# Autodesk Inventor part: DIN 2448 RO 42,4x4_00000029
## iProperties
Created: 2006-02
Part Number: DIN 2448 RO 42,4x4_00000029
Material: Default
Document SubType Name: Modeling
Designer: FranzK
Stock Number: DIN 2448 RO 42,4x4
Mass: 421.965 g
Surface Area: 2123.47 cm^2
Volume: 421.965 cm^3
Density: 1 g/cm^3
G_L: 890.000 mm
G_W: 42.400 mm
G_H: 42.400 mm
AFG_Item: 42.4 x 4
CSToolsMass: 0.4
CSToolsVolume: 421965.0
CSToolsArea: 2123.0
Author: FranzK
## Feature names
1. AFG_Detailed_DIN 2448 RO 42,4x4_00000029 [Extrusion]
2. AFG_Simplified_DIN 2448 RO 42,4x4_00000029 [Extrusion]
3. AFG_EndExtrusion_1 [Extrusion]
4. AFG_EndExtrusion_2 [Extrusion]
